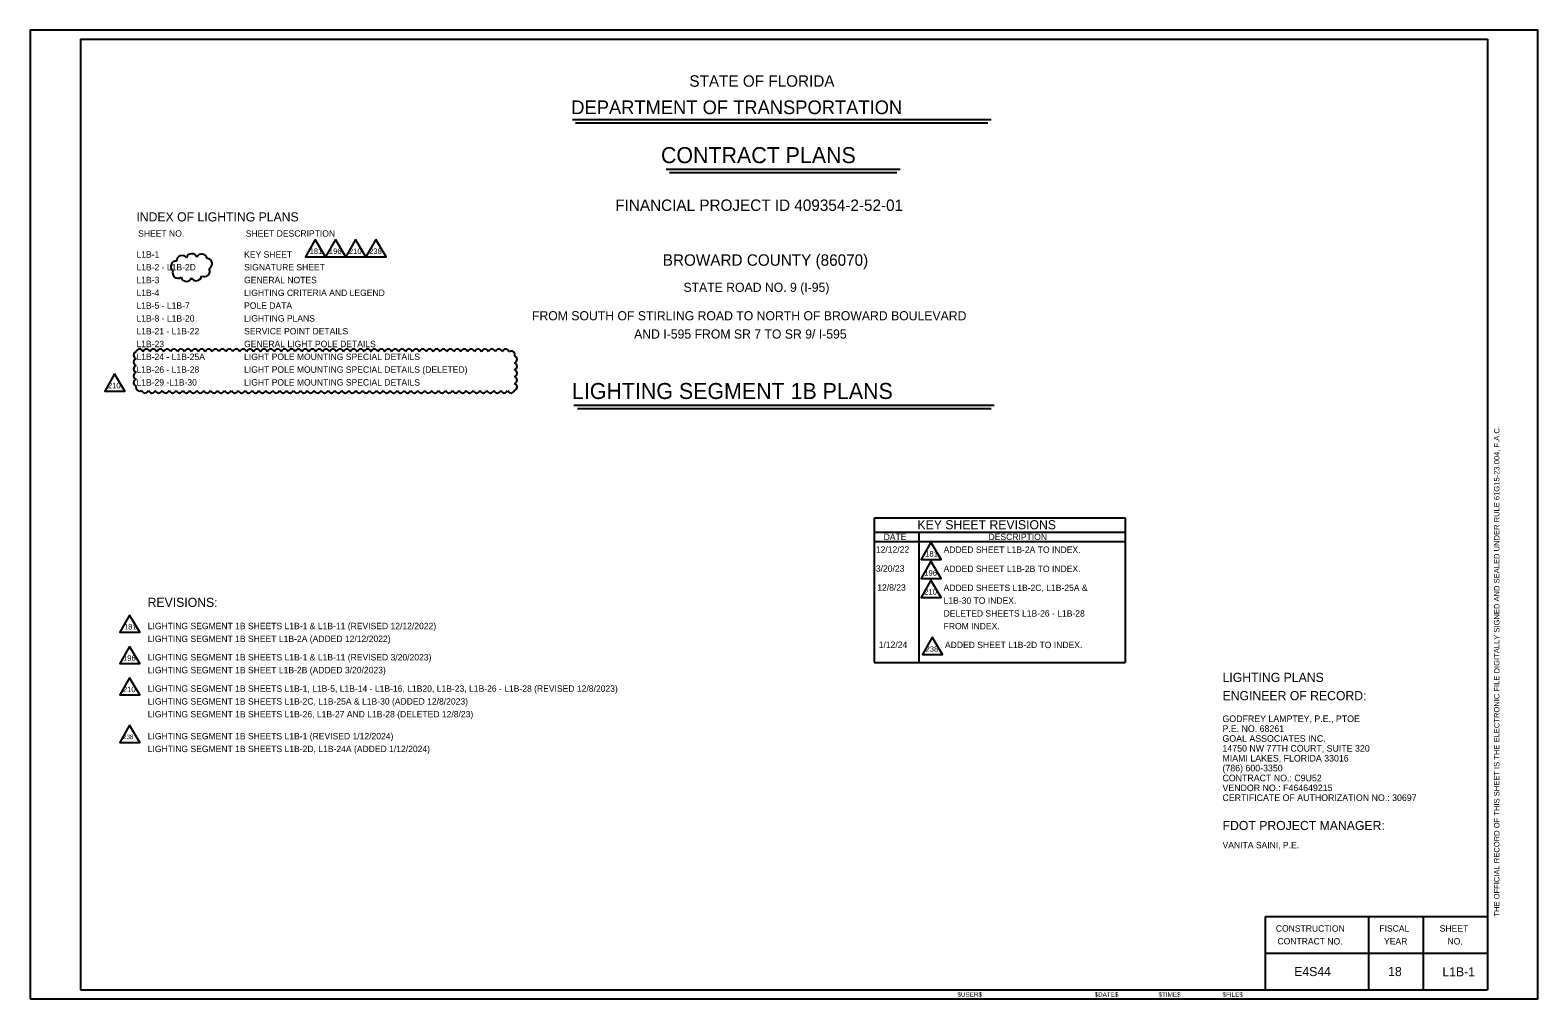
# Model space of a CAD drawing. Extents: x -818.6 to -802.1, y -2197.9 to -2175.
# Drawn here: x -818.56 to -802.06, y -2197.92 to -2187.32 of the extents above; entities that cross this region are included whole.
import ezdxf

# ---------------------------------------------------------------- set-up
doc = ezdxf.new("R2010")
doc.units = 0
for name, color, linetype in [('ActivePointCell_dp', 7, 'Continuous'), ('Cloud_dp', 7, 'Continuous'), ('PlotBorder_dp', 7, 'Continuous'), ('SheetBorder_dp', 7, 'Continuous'), ('SheetLines_dp', 7, 'Continuous'), ('SumBoxLines_dp', 7, 'Continuous'), ('TextLabel', 7, 'Continuous'), ('TextMinor', 7, 'Continuous'), ('TextMisc', 7, 'Continuous'), ('TextNotes', 7, 'Continuous'), ('TextShtNo', 7, 'Continuous'), ('TextTitle', 7, 'Continuous')]:
    doc.layers.add(name, color=color, linetype=linetype)

msp = doc.modelspace()

# ---------------------------------------------------------------- linework, layer by layer
at = {"layer": 'ActivePointCell_dp'}
msp.add_line((-802.614, -2187.419), (-802.614, -2187.419), dxfattribs=at)
at = {"layer": 'Cloud_dp'}
for points in [[(-815.443, -2189.61), (-815.551, -2189.798), (-815.33, -2189.798)], [(-815.222, -2189.61), (-815.33, -2189.798), (-815.109, -2189.798)], [(-815.002, -2189.61), (-815.109, -2189.798), (-814.889, -2189.798)], [(-814.781, -2189.61), (-814.889, -2189.798), (-814.668, -2189.798)], [(-817.639, -2191.08), (-817.746, -2191.268), (-817.526, -2191.268)], [(-808.706, -2192.922), (-808.814, -2193.11), (-808.593, -2193.11)], [(-808.706, -2193.13), (-808.814, -2193.318), (-808.593, -2193.318)], [(-808.706, -2193.338), (-808.814, -2193.526), (-808.593, -2193.526)], [(-817.475, -2193.719), (-817.583, -2193.907), (-817.362, -2193.907)], [(-808.691, -2193.963), (-808.799, -2194.151), (-808.578, -2194.151)], [(-817.475, -2194.062), (-817.583, -2194.25), (-817.362, -2194.25)], [(-817.475, -2194.405), (-817.583, -2194.593), (-817.362, -2194.593)], [(-817.475, -2194.924), (-817.583, -2195.113), (-817.362, -2195.113)]]:
    msp.add_lwpolyline(points, close=True, dxfattribs=at)
for centre, radius, start, end in [((-816.966, -2189.905), 0.0599, 86.9907, 231.9907), ((-816.902, -2189.845), 0.06, 35.4166, 180.4166), ((-816.795, -2189.825), 0.0599, 21.2778, 166.2778), ((-816.685, -2189.828), 0.0599, 9.9863, 154.9863), ((-816.632, -2189.877), 0.0599, 298.9542, 83.9542), ((-816.946, -2189.974), 0.0599, 159.4236, 304.4236), ((-816.854, -2190.008), 0.0599, 194.4381, 339.4381), ((-816.745, -2190.001), 0.0599, 207.5787, 352.5787), ((-816.657, -2189.957), 0.0599, 241.4449, 26.4449), ((-817.392, -2190.875), 0.0396, 107.5, 252.5), ((-817.366, -2190.849), 0.0396, 17.5, 162.5), ((-817.291, -2190.849), 0.0396, 17.5, 162.5), ((-817.215, -2190.849), 0.0396, 17.5, 162.5), ((-817.139, -2190.849), 0.0396, 17.5, 162.5), ((-817.064, -2190.849), 0.0396, 17.5, 162.5), ((-816.988, -2190.849), 0.0396, 17.5, 162.5), ((-816.913, -2190.849), 0.0396, 17.5, 162.5), ((-816.837, -2190.849), 0.0396, 17.5, 162.5), ((-816.761, -2190.849), 0.0396, 17.5, 162.5), ((-816.686, -2190.849), 0.0396, 17.5, 162.5), ((-816.61, -2190.849), 0.0396, 17.5, 162.5), ((-816.535, -2190.849), 0.0396, 17.5, 162.5), ((-816.459, -2190.849), 0.0396, 17.5, 162.5), ((-816.383, -2190.849), 0.0396, 17.5, 162.5), ((-816.308, -2190.849), 0.0396, 17.5, 162.5), ((-816.232, -2190.849), 0.0396, 17.5, 162.5), ((-816.157, -2190.849), 0.0396, 17.5, 162.5), ((-816.081, -2190.849), 0.0396, 17.5, 162.5), ((-816.005, -2190.849), 0.0396, 17.5, 162.5), ((-815.93, -2190.849), 0.0396, 17.5, 162.5), ((-815.854, -2190.849), 0.0396, 17.5, 162.5), ((-815.779, -2190.849), 0.0396, 17.5, 162.5), ((-815.703, -2190.849), 0.0396, 17.5, 162.5), ((-815.627, -2190.849), 0.0396, 17.5, 162.5), ((-815.552, -2190.849), 0.0396, 17.5, 162.5), ((-815.476, -2190.849), 0.0396, 17.5, 162.5), ((-815.401, -2190.849), 0.0396, 17.5, 162.5), ((-815.325, -2190.849), 0.0396, 17.5, 162.5), ((-815.249, -2190.849), 0.0396, 17.5, 162.5), ((-815.174, -2190.849), 0.0396, 17.5, 162.5), ((-815.098, -2190.849), 0.0396, 17.5, 162.5), ((-815.023, -2190.849), 0.0396, 17.5, 162.5), ((-814.947, -2190.849), 0.0396, 17.5, 162.5), ((-814.871, -2190.849), 0.0396, 17.5, 162.5), ((-814.796, -2190.849), 0.0396, 17.5, 162.5), ((-814.72, -2190.849), 0.0396, 17.5, 162.5), ((-814.645, -2190.849), 0.0396, 17.5, 162.5), ((-814.569, -2190.849), 0.0396, 17.5, 162.5), ((-814.493, -2190.849), 0.0396, 17.5, 162.5), ((-814.418, -2190.849), 0.0396, 17.5, 162.5), ((-814.342, -2190.849), 0.0396, 17.5, 162.5), ((-814.267, -2190.849), 0.0396, 17.5, 162.5), ((-814.191, -2190.849), 0.0396, 17.5, 162.5), ((-814.115, -2190.849), 0.0396, 17.5, 162.5), ((-814.04, -2190.849), 0.0396, 17.5, 162.5), ((-813.964, -2190.849), 0.0396, 17.5, 162.5), ((-813.889, -2190.849), 0.0396, 17.5, 162.5), ((-813.813, -2190.849), 0.0396, 17.5, 162.5), ((-813.737, -2190.849), 0.0396, 17.5, 162.5), ((-813.662, -2190.849), 0.0396, 17.5, 162.5), ((-813.586, -2190.849), 0.0396, 17.5, 162.5), ((-813.511, -2190.849), 0.0396, 17.5, 162.5), ((-813.435, -2190.849), 0.0396, 17.5, 162.5), ((-813.359, -2190.849), 0.0396, 17.5, 162.5), ((-813.299, -2190.87), 0.0396, 339.0908, 124.0908), ((-817.392, -2190.951), 0.0396, 107.5, 252.5), ((-817.392, -2191.026), 0.0396, 107.5, 252.5), ((-813.274, -2190.922), 0.0396, 287.5, 72.5), ((-813.274, -2190.998), 0.0396, 287.5, 72.5), ((-817.392, -2191.102), 0.0396, 107.5, 252.5), ((-817.392, -2191.177), 0.0396, 107.5, 252.5), ((-813.274, -2191.073), 0.0396, 287.5, 72.5), ((-813.274, -2191.149), 0.0396, 287.5, 72.5), ((-813.274, -2191.224), 0.0396, 287.5, 72.5), ((-817.367, -2191.229), 0.0396, 159.0908, 304.0908), ((-817.307, -2191.25), 0.0396, 197.5, 342.5), ((-817.231, -2191.25), 0.0396, 197.5, 342.5), ((-817.156, -2191.25), 0.0396, 197.5, 342.5), ((-817.08, -2191.25), 0.0396, 197.5, 342.5), ((-817.005, -2191.25), 0.0396, 197.5, 342.5), ((-816.929, -2191.25), 0.0396, 197.5, 342.5), ((-816.853, -2191.25), 0.0396, 197.5, 342.5), ((-816.778, -2191.25), 0.0396, 197.5, 342.5), ((-816.702, -2191.25), 0.0396, 197.5, 342.5), ((-816.627, -2191.25), 0.0396, 197.5, 342.5), ((-816.551, -2191.25), 0.0396, 197.5, 342.5), ((-816.475, -2191.25), 0.0396, 197.5, 342.5), ((-816.4, -2191.25), 0.0396, 197.5, 342.5), ((-816.324, -2191.25), 0.0396, 197.5, 342.5), ((-816.249, -2191.25), 0.0396, 197.5, 342.5), ((-816.173, -2191.25), 0.0396, 197.5, 342.5), ((-816.097, -2191.25), 0.0396, 197.5, 342.5), ((-816.022, -2191.25), 0.0396, 197.5, 342.5), ((-815.946, -2191.25), 0.0396, 197.5, 342.5), ((-815.871, -2191.25), 0.0396, 197.5, 342.5), ((-815.795, -2191.25), 0.0396, 197.5, 342.5), ((-815.719, -2191.25), 0.0396, 197.5, 342.5), ((-815.644, -2191.25), 0.0396, 197.5, 342.5), ((-815.568, -2191.25), 0.0396, 197.5, 342.5), ((-815.493, -2191.25), 0.0396, 197.5, 342.5), ((-815.417, -2191.25), 0.0396, 197.5, 342.5), ((-815.341, -2191.25), 0.0396, 197.5, 342.5), ((-815.266, -2191.25), 0.0396, 197.5, 342.5), ((-815.19, -2191.25), 0.0396, 197.5, 342.5), ((-815.115, -2191.25), 0.0396, 197.5, 342.5), ((-815.039, -2191.25), 0.0396, 197.5, 342.5), ((-814.963, -2191.25), 0.0396, 197.5, 342.5), ((-814.888, -2191.25), 0.0396, 197.5, 342.5), ((-814.812, -2191.25), 0.0396, 197.5, 342.5), ((-814.737, -2191.25), 0.0396, 197.5, 342.5), ((-814.661, -2191.25), 0.0396, 197.5, 342.5), ((-814.585, -2191.25), 0.0396, 197.5, 342.5), ((-814.51, -2191.25), 0.0396, 197.5, 342.5), ((-814.434, -2191.25), 0.0396, 197.5, 342.5), ((-814.359, -2191.25), 0.0396, 197.5, 342.5), ((-814.283, -2191.25), 0.0396, 197.5, 342.5), ((-814.207, -2191.25), 0.0396, 197.5, 342.5), ((-814.132, -2191.25), 0.0396, 197.5, 342.5), ((-814.056, -2191.25), 0.0396, 197.5, 342.5), ((-813.981, -2191.25), 0.0396, 197.5, 342.5), ((-813.905, -2191.25), 0.0396, 197.5, 342.5), ((-813.829, -2191.25), 0.0396, 197.5, 342.5), ((-813.754, -2191.25), 0.0396, 197.5, 342.5), ((-813.678, -2191.25), 0.0396, 197.5, 342.5), ((-813.603, -2191.25), 0.0396, 197.5, 342.5), ((-813.527, -2191.25), 0.0396, 197.5, 342.5), ((-813.451, -2191.25), 0.0396, 197.5, 342.5), ((-813.376, -2191.25), 0.0396, 197.5, 342.5), ((-813.3, -2191.25), 0.0396, 197.5, 342.5)]:
    msp.add_arc(centre, radius, start, end, dxfattribs=at)
at = {"layer": 'PlotBorder_dp'}
msp.add_lwpolyline([(-818.564, -2197.919), (-802.064, -2197.919), (-802.064, -2187.319), (-818.564, -2187.319)], close=True, dxfattribs=at)
at = {"layer": 'SheetBorder_dp'}
for p, q in [((-818.014, -2187.419), (-818.014, -2197.819)), ((-818.014, -2187.419), (-802.614, -2187.419)), ((-802.614, -2187.419), (-802.614, -2197.819)), ((-818.014, -2197.819), (-802.614, -2197.819))]:
    msp.add_line(p, q, dxfattribs=at)
at = {"layer": 'SheetLines_dp'}
for p, q in [((-805.044, -2197.019), (-802.614, -2197.019)), ((-805.044, -2197.819), (-805.044, -2197.019)), ((-803.914, -2197.819), (-803.914, -2197.019)), ((-803.314, -2197.819), (-803.314, -2197.019)), ((-805.044, -2197.419), (-802.614, -2197.419))]:
    msp.add_line(p, q, dxfattribs=at)
at = {"layer": 'SumBoxLines_dp'}
for p, q in [((-809.327, -2192.654), (-809.327, -2194.237)), ((-809.327, -2192.654), (-806.58, -2192.654)), ((-806.58, -2192.654), (-806.58, -2194.237)), ((-809.327, -2192.814), (-806.58, -2192.814)), ((-808.837, -2192.814), (-808.837, -2194.237)), ((-809.327, -2192.914), (-806.58, -2192.914)), ((-809.327, -2194.237), (-806.58, -2194.237))]:
    msp.add_line(p, q, dxfattribs=at)
at = {"layer": 'TextTitle'}
for p, q in [((-812.63, -2188.295), (-808.048, -2188.295)), ((-812.597, -2188.333), (-808.083, -2188.333)), ((-811.605, -2188.84), (-809.044, -2188.84)), ((-811.566, -2188.878), (-809.077, -2188.878)), ((-812.614, -2191.421), (-808.015, -2191.421)), ((-812.575, -2191.459), (-808.047, -2191.459))]:
    msp.add_line(p, q, dxfattribs=at)

# ---------------------------------------------------------------- texts
at = {"layer": 'Cloud_dp'}
for s, height, p in [('181', 0.06, (-815.505, -2189.768)), ('196', 0.06, (-815.294, -2189.768)), ('210', 0.06, (-815.075, -2189.768)), ('238', 0.06, (-814.854, -2189.768)), ('210', 0.06, (-817.712, -2191.238)), ('181', 0.06, (-808.768, -2193.079)), ('196', 0.06, (-808.778, -2193.288)), ('210', 0.06, (-808.779, -2193.496)), ('181', 0.06, (-817.537, -2193.877)), ('196', 0.06, (-817.547, -2194.22)), ('238', 0.06, (-808.764, -2194.121)), ('210', 0.06, (-817.548, -2194.563)), ('238', 0.05, (-817.548, -2195.077))]:
    msp.add_text(s, height=height, rotation=0, dxfattribs=at).set_placement(p)
at = {"layer": 'TextLabel'}
for s, height, p in [('FINANCIAL PROJECT ID 409354-2-52-01', 0.125, (-812.16, -2189.297)), ('INDEX OF LIGHTING PLANS', 0.1, (-817.401, -2189.412)), ('L1B-1', 0.07, (-817.4, -2189.808)), ('L1B-2 - L1B-2D', 0.07, (-817.4, -2189.948)), ('SIGNATURE SHEET', 0.07, (-816.222, -2189.948)), ('KEY SHEET', 0.07, (-816.222, -2189.808)), ('BROWARD COUNTY (86070)', 0.125, (-811.64, -2189.897)), ('L1B-3', 0.07, (-817.4, -2190.088)), ('GENERAL NOTES', 0.07, (-816.222, -2190.088)), ('L1B-4', 0.07, (-817.4, -2190.228)), ('LIGHTING CRITERIA AND LEGEND', 0.07, (-816.222, -2190.228)), ('STATE ROAD NO. 9 (I-95)', 0.1, (-811.414, -2190.183)), ('L1B-5 - L1B-7', 0.07, (-817.4, -2190.368)), ('POLE DATA', 0.07, (-816.222, -2190.368)), ('L1B-8 - L1B-20', 0.07, (-817.4, -2190.508)), ('LIGHTING PLANS', 0.07, (-816.222, -2190.508)), ('FROM SOUTH OF STIRLING ROAD TO NORTH OF BROWARD BOULEVARD', 0.1, (-813.072, -2190.494)), ('L1B-21 - L1B-22', 0.07, (-817.4, -2190.648)), ('SERVICE POINT DETAILS', 0.07, (-816.222, -2190.648)), ('AND I-595 FROM SR 7 TO SR 9/ I-595', 0.1, (-811.954, -2190.694)), ('L1B-23', 0.07, (-817.4, -2190.788)), ('L1B-24 - L1B-25A', 0.07, (-817.4, -2190.928)), ('GENERAL LIGHT POLE DETAILS', 0.07, (-816.222, -2190.788)), ('LIGHT POLE MOUNTING SPECIAL DETAILS', 0.07, (-816.222, -2190.928)), ('L1B-26 - L1B-28', 0.07, (-817.4, -2191.068)), ('LIGHT POLE MOUNTING SPECIAL DETAILS (DELETED)', 0.07, (-816.222, -2191.068)), ('L1B-29 -L1B-30', 0.07, (-817.4, -2191.208)), ('LIGHT POLE MOUNTING SPECIAL DETAILS', 0.07, (-816.222, -2191.208)), ('KEY SHEET REVISIONS', 0.1, (-808.853, -2192.781)), ('REVISIONS:', 0.1, (-817.278, -2193.63)), ('LIGHTING PLANS', 0.1, (-805.514, -2194.451)), ('ENGINEER OF RECORD:', 0.1, (-805.514, -2194.651)), ('GODFREY LAMPTEY, P.E., PTOE', 0.07202, (-805.515, -2194.89)), ('P.E. NO. 68261', 0.07202, (-805.515, -2194.998)), ('GOAL ASSOCIATES INC. ', 0.07202, (-805.515, -2195.106)), ('14750 NW 77TH COURT, SUITE 320', 0.07202, (-805.515, -2195.214)), ('MIAMI LAKES, FLORIDA 33016', 0.07202, (-805.515, -2195.322)), ('CONTRACT NO.: C9U52', 0.07202, (-805.515, -2195.538)), ('(786) 600-3350', 0.07202, (-805.515, -2195.43)), ('VENDOR NO.: F464649215', 0.07202, (-805.515, -2195.646)), ('CERTIFICATE OF AUTHORIZATION NO.: 30697', 0.07202, (-805.515, -2195.754)), ('E4S44', 0.1, (-804.73, -2197.67)), ('18', 0.1, (-803.702, -2197.67))]:
    msp.add_text(s, height=height, dxfattribs=at).set_placement(p)
at = {"layer": 'TextMinor'}
for s, height, p in [('12/12/22', 0.07, (-809.308, -2193.037)), ('ADDED SHEET L1B-2A TO INDEX.', 0.07, (-808.567, -2193.039)), ('3/20/23', 0.07, (-809.308, -2193.245)), ('ADDED SHEET L1B-2B TO INDEX.', 0.07, (-808.567, -2193.248)), ('12/8/23', 0.07, (-809.293, -2193.453)), ('ADDED SHEETS L1B-2C, L1B-25A & ', 0.07, (-808.567, -2193.456)), ('L1B-30 TO INDEX.', 0.07, (-808.567, -2193.596)), ('DELETED SHEETS L1B-26 - L1B-28 ', 0.07, (-808.567, -2193.736)), ('FROM INDEX.', 0.07, (-808.567, -2193.876)), ('1/12/24', 0.07, (-809.277, -2194.079)), ('ADDED SHEET L1B-2D TO INDEX.', 0.07, (-808.552, -2194.081)), ('$USER$', 0.05, (-808.415, -2197.897))]:
    msp.add_text(s, height=height, dxfattribs=at).set_placement(p)
for s, p in [('$DATE$', (-806.915, -2197.897)), ('$TIME$', (-806.215, -2197.897)), ('$FILE$', (-805.515, -2197.897))]:
    msp.add_text(s, height=0.05, rotation=360, dxfattribs=at).set_placement(p)
at = {"layer": 'TextMisc'}
msp.add_text('THE OFFICIAL RECORD OF THIS SHEET IS THE ELECTRONIC FILE DIGITALLY SIGNED AND SEALED UNDER RULE 61G15-23.004, F.A.C.', height=0.06, rotation=90, dxfattribs=at).set_placement((-802.484, -2197.019))
at = {"layer": 'TextNotes'}
for s, height, p in [('SHEET NO.', 0.07, (-817.382, -2189.579)), ('SHEET DESCRIPTION', 0.07, (-816.204, -2189.579)), ('DATE', 0.07, (-809.223, -2192.899)), ('DESCRIPTION', 0.07, (-808.075, -2192.899)), ('LIGHTING SEGMENT 1B SHEETS L1B-1 & L1B-11 (REVISED 12/12/2022)', 0.06998, (-817.277, -2193.874)), ('LIGHTING SEGMENT 1B SHEET L1B-2A (ADDED 12/12/2022)', 0.06998, (-817.277, -2194.014)), ('LIGHTING SEGMENT 1B SHEETS L1B-1 & L1B-11 (REVISED 3/20/2023)', 0.06998, (-817.277, -2194.216)), ('LIGHTING SEGMENT 1B SHEET L1B-2B (ADDED 3/20/2023)', 0.06998, (-817.277, -2194.356)), ('LIGHTING SEGMENT 1B SHEETS L1B-1, L1B-5, L1B-14 - L1B-16, L1B20, L1B-23, L1B-26 - L1B-28 (REVISED 12/8/2023)', 0.069982, (-817.277, -2194.559)), ('LIGHTING SEGMENT 1B SHEETS L1B-2C, L1B-25A & L1B-30 (ADDED 12/8/2023)', 0.06998, (-817.277, -2194.699)), ('LIGHTING SEGMENT 1B SHEETS L1B-26, L1B-27 AND L1B-28 (DELETED 12/8/23)', 0.06998, (-817.277, -2194.839)), ('LIGHTING SEGMENT 1B SHEETS L1B-1 (REVISED 1/12/2024)', 0.06998, (-817.277, -2195.079)), ('LIGHTING SEGMENT 1B SHEETS L1B-2D, L1B-24A (ADDED 1/12/2024)', 0.06998, (-817.277, -2195.219)), ('FDOT PROJECT MANAGER:', 0.1, (-805.514, -2196.072)), ('VANITA SAINI, P.E.', 0.07, (-805.514, -2196.271))]:
    msp.add_text(s, height=height, dxfattribs=at).set_placement(p)
for s, p in [('CONSTRUCTION', (-804.931, -2197.183)), ('FISCAL', (-803.798, -2197.183)), ('SHEET', (-803.138, -2197.183)), ('CONTRACT NO.', (-804.913, -2197.323)), ('YEAR', (-803.747, -2197.324)), ('NO.', (-803.052, -2197.324))]:
    msp.add_text(s, height=0.07, rotation=359.8607, dxfattribs=at).set_placement(p)
at = {"layer": 'TextShtNo'}
msp.add_text('L1B-1', height=0.1, dxfattribs=at).set_placement((-803.108, -2197.673))
at = {"layer": 'TextTitle'}
for s, height, p in [('STATE OF FLORIDA', 0.125, (-811.349, -2187.938)), ('DEPARTMENT OF TRANSPORTATION', 0.15, (-812.642, -2188.238)), ('CONTRACT PLANS', 0.175, (-811.66, -2188.774)), ('LIGHTING SEGMENT 1B PLANS', 0.175, (-812.634, -2191.355))]:
    msp.add_text(s, height=height, dxfattribs=at).set_placement(p)

doc.saveas('drawing.dxf')
